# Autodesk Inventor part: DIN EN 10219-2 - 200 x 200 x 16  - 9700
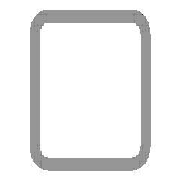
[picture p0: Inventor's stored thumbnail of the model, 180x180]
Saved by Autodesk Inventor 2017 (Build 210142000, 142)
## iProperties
IsCustomPart: 1
Created: 2017-11
Part Number: DIN EN 10219-2 - 200 x 200 x 16  - 9700
Material: Steel, Mild
Description: Cold formed welded structural hollow sections of non-alloy and fine grain structural steel
Document SubType Name: Modeling
Standard: DIN
Designer: iusti
Standard Revision: 2006-07
Standards Organization: DIN
Language: en-US
Size Designation: 200 x 200 x 16
Categories: <MemberInstance><Categories><Category DisplayName="Structural Shapes" InternalName="089c4875-fa83-4c05-b084-43b9cc11f5ed" Mnemonic="GRDR"><CategoryParameter Dis
Stock Number: 200 x 200 x 16
Density: 7.85 g/cm^3
Appearance: Semi-Polished
Mass: 796255 g
Surface Area: 127094 cm^2
Volume: 101434 cm^3
_CCFamilyMember: 103
_CCFamilyDisplayName: DIN EN 10219-2 (Square Hollow Section - Cold Formed) - Cold formed welded structural hollow sections of non-alloy and fine grain structural steel
_FrameMemberDoc: Frame Member File
_Version: 15.0.0
_GetPNFromCC: 1
G_L: 9700.000 mm
G_W: 200.000 mm
G_H: 200.000 mm
+A69F4663-CFB7-4D18-824B-3D97B0B5E8F0+CUTDETAIL1: Cut
+26595D0A-3E89-4A2F-9DA7-6BDC5E0BE6FD+CUTDETAIL2: Cut
+81F2769D-CBCB-4BAE-9991-99821565208A+CUTDETAIL3: Miter 45.00 deg
+B125B8ED-1570-405A-A825-64B3EFBC6DC3+CUTDETAIL4: Miter 45.00 deg
Author: iusti
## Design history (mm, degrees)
node "Start plane"
node "End plane"
sketch "Sketch"
  geometry: L1 (-100, -52)-(-100, 52); L2 (-52, 100)-(52, 100); L3 (100, 52)-(100, -52); L4 (52, -100)-(-52, -100); L5 (-52, 84)-(52, 84); L6 (84, 52)-(84, -52); L7 (52, -84)-(-52, -84); L8 (-84, -52)-(-84, 52); L9 (0, 153.918)-(0, -153.918) reference; L10 (-153.918, 0)-(153.918, 0) reference; A1 r 48 centre (-52, -52) between (-100, -52) and (-52, -100); A2 r 48 centre (-52, 52) between (-52, 100) and (-100, 52); A3 r 48 centre (52, 52) between (100, 52) and (52, 100); A4 r 48 centre (52, -52) between (52, -100) and (100, -52); A5 r 32 centre (-52, 52) between (-52, 84) and (-84, 52); A6 r 32 centre (52, 52) between (84, 52) and (52, 84); A7 r 32 centre (52, -52) between (52, -84) and (84, -52); A8 r 32 centre (-52, -52) between (-84, -52) and (-52, -84)
  constraints: 16 end point, 16 point on circle, 8 centre point, 8 tangent, 4 parallel, 3 equal radius, 2 perpendicular, 7 other
  dimensions: "d7" = 48 radius of A1 (= G_IR); "d10" = 200 distance between parallel lines of L2 L4 (= G_H); "d11" = 200 distance between parallel lines of L1 L3 (= G_W); "d12" = 16 distance between parallel lines of L3 L6 (= G_T); "d15" = 100 distance between parallel lines of L2 L10 (= 0.5 x d10); "d16" = 100 distance between parallel lines of L9 L3 (= 0.5 x d11)
extrude "Body" new body sketch "Sketch" stored distance "d3" = 9700 (= G_L); taper "d4" = 0 deg
node "Driven Length"
  sketch "Sketch3"
    geometry: L1 (0, 0)-(10, 0) reference
    constraints: 2 end point, 1 horizontal
  workplane "Work Plane3"
  sketch "Sketch4"
    geometry: L1 (-2, -100)-(12, -100) reference; L2 (-2, 9600)-(12, 9600) reference
    dimensions: "d18" = 9700 distance between parallel lines of L1 L2 (derived)
workplane "Work Plane4"
split "Split1"
workplane "Work Plane5"
split "Split2"
workplane "Work Plane6"
split "Split3"
workplane "Work Plane7"
split "Split4"
body "Solid1"
other parameters: "G_W" = 200 [user parameter; used in 1 equation term], "G_H" = 200 [user parameter; used in 1 equation term], "G_T" = 16 [user parameter; used in 1 equation term], "G_IR" = 48 [user parameter; used in 1 equation term], "G_L" = 9700 (= d18) [user parameter; used in 1 equation term], "d17" = 90 deg
